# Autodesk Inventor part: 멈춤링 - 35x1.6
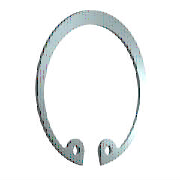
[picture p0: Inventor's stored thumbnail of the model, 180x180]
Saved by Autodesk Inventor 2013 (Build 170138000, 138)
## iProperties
IsCustomPart: 1
Created: 2015-09
Part Number: 멈춤링 - 35x1.6
Material: 강철, 연강
Description: 리테이닝 링(C형)
Document SubType Name: Modeling
Standard: KS B 1336
Designer: mduedu
Standards Organization: KS
Language: ko-KR
Size Designation: 35x1.6
Categories: <MemberInstance><Categories><Category DisplayName="샤프트 부품" InternalName="7f7aeb1f-a693-4053-b835-cee3144e0d98" Mnemonic="SHFT"><Category DisplayName="써클립" Inter
Density: 7.86 g/cm^3
Mass: 3.5371 g
Surface Area: 9.09651 cm^2
Volume: 0.450013 cm^3
Author: mduedu
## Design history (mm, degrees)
sketch "스케치1"
  geometry: L1 (0, 15.113)-(0, -73.177) reference; L2 (-45.5, 0)-(45.5, 0) reference; L3 (-4.964, 1)-(1.502, 1); L4 (0, -2.5)-(-5.307, -2.5); L5 (0, -17.5)-(-8.583, -33.888); L6 (-8.583, -33.888)-(-21.772, -26.981); L7 (-7.377, -31.585)-(-17.631, -26.214); L8 (-5.162, -32.745)-(-6.29, -34.898); L9 (5.162, -32.745)-(6.29, -34.898); C1 r 1.25 at (-7.377, -31.585); C2 r 1.25 at (7.377, -31.585); A1 r 15.875 centre (0, -18.375) between (11.82, -28.972) and (-11.82, -28.972); A2 r 18.5 centre (0, -17.5) between (6.29, -34.898) and (-6.29, -34.898); A3 r 2.5 centre (-7.377, -31.585) between (-5.162, -32.745) and (-8.668, -29.444); A4 r 2.5 centre (-9.959, -27.303) between (-11.82, -28.972) and (-8.668, -29.444); A5 r 2.5 centre (9.959, -27.303) between (8.668, -29.444) and (11.82, -28.972); A6 r 2.5 centre (7.377, -31.585) between (8.668, -29.444) and (5.162, -32.745); 3 further points
  constraints: 15 point on circle, 14 end point, 9 symmetric about line, 8 centre point, 6 tangent, 4 coincident, 4 point on line, 3 perpendicular, 1 parallel, 4 other
  dimensions: "d8" = 0.875 distance of A1.centre L5.start (= 0.25 x SRB1); "d38" = 3.5 distance between parallel lines of L4 L3 (= SRB1); "d39" = 17.5 distance from line of L5.start L2 (= 0.5 x WD); "d43" = 18.5 radius of A2 (= 0.5 x ND); "d45" = 2.6 distance between parallel lines of L7 L6 (= 0.5 x SRB2); "d46" = 2.5 radius of A4 (= SD5); "d47" = 6.29 distance from line of L1 L8.end (= 0.17 x ND); "d48" = 2.5 diameter of C1 (= SD5); "d49" = 2.5 radius of A3 (= SD5)
extrude "본체" new body sketch "스케치1" distance "d2" = 1.6 (= SD); taper "d3" = 0 deg
workaxis "Work Axis1"
workaxis "Work Axis2"
workplane "Work Plane1"
body "Solid1"
other parameters: "WD" = 35 [user parameter; used in 3 equation terms], "SD" = 1.6 [user parameter; used in 1 equation term], "SRB1" = 3.5 [user parameter; used in 2 equation terms], "ND" = 37 [user parameter; used in 2 equation terms], "SRB2" = 5.2 [user parameter; used in 1 equation term], "SD5" = 2.5 [user parameter; used in 3 equation terms], "d50" = 0, "d51" = 0, "d52" = 0, "d53" = 0, "WDMIN" = 34 [user parameter], "SD6" = 37.8 [user parameter], "WDMAX" = 35 (= WD) [user parameter], "NND" = 35 (= WD) [user parameter]
